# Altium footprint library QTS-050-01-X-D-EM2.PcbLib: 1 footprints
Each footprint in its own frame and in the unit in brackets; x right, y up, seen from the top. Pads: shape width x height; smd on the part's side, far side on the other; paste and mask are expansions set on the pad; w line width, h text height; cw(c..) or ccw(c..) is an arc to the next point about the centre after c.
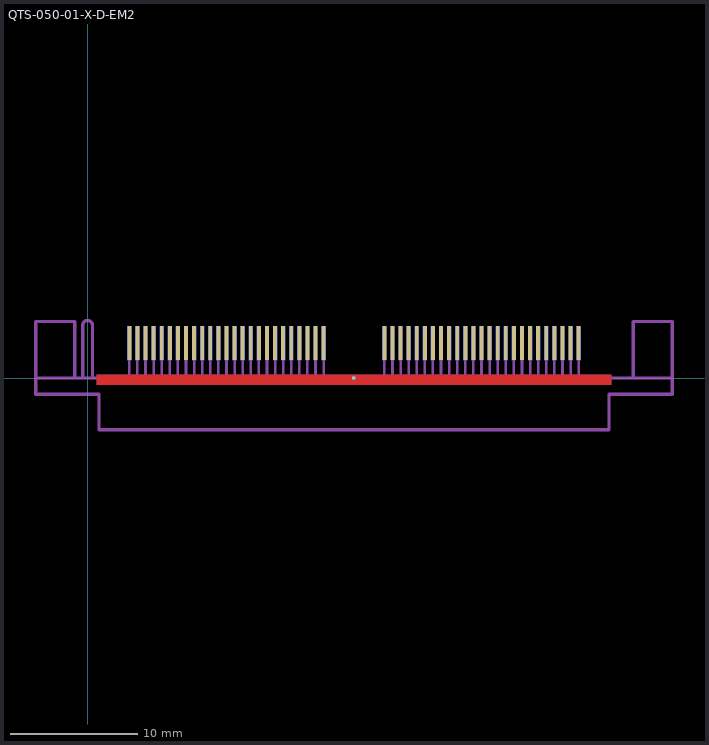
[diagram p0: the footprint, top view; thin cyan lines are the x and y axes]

## QTS-050-01-X-D-EM2 [mil] "0.635mm pitch, 100 pin, high speed terminal; w/edge mounts"
height 117.72
pads (102):
  rect 12x105 smd mask+0: 1(128.8,107.5) 3(153.8,107.5) 5(178.8,107.5) 7(203.8,107.5) 9(228.8,107.5) 11(253.8,107.5) 13(278.8,107.5) 15(303.8,107.5) 17(328.8,107.5) 19(353.8,107.5) 21(378.8,107.5) 23(403.8,107.5) 25(428.8,107.5) 27(453.8,107.5) 29(478.8,107.5) 31(503.8,107.5) 33(528.8,107.5) 35(553.8,107.5) 37(578.8,107.5) 39(603.8,107.5) 41(628.8,107.5) 43(653.8,107.5) 45(678.8,107.5) 47(703.8,107.5) 49(728.8,107.5) 51(916.3,107.5) 53(941.3,107.5) 55(966.3,107.5) 57(991.3,107.5) 59(1016.3,107.5) 61(1041.3,107.5) 63(1066.3,107.5) 65(1091.3,107.5) 67(1116.3,107.5) 69(1141.3,107.5) 71(1166.3,107.5) 73(1191.3,107.5) 75(1216.3,107.5) 77(1241.3,107.5) 79(1266.3,107.5) 81(1291.3,107.5) 83(1316.3,107.5) 85(1341.3,107.5) 87(1366.3,107.5) 89(1391.3,107.5) 91(1416.3,107.5) 93(1441.3,107.5) 95(1466.3,107.5) 97(1491.3,107.5) 99(1516.3,107.5)
  rect 12x105 smd far side mask+0: 2(128.8,107.5) 4(153.8,107.5) 6(178.8,107.5) 8(203.8,107.5) 10(228.8,107.5) 12(253.8,107.5) 14(278.8,107.5) 16(303.8,107.5) 18(328.8,107.5) 20(353.8,107.5) 22(378.8,107.5) 24(403.8,107.5) 26(428.8,107.5) 28(453.8,107.5) 30(478.8,107.5) 32(503.8,107.5) 34(528.8,107.5) 36(553.8,107.5) 38(578.8,107.5) 40(603.8,107.5) 42(628.8,107.5) 44(653.8,107.5) 46(678.8,107.5) 48(703.8,107.5) 50(728.8,107.5) 52(916.3,107.5) 54(941.3,107.5) 56(966.3,107.5) 58(991.3,107.5) 60(1016.3,107.5) 62(1041.3,107.5) 64(1066.3,107.5) 66(1091.3,107.5) 68(1116.3,107.5) 70(1141.3,107.5) 72(1166.3,107.5) 74(1191.3,107.5) 76(1216.3,107.5) 78(1241.3,107.5) 80(1266.3,107.5) 82(1291.3,107.5) 84(1316.3,107.5) 86(1341.3,107.5) 88(1366.3,107.5) 90(1391.3,107.5) 92(1416.3,107.5) 94(1441.3,107.5) 96(1466.3,107.5) 98(1491.3,107.5) 100(1516.3,107.5)
  rect 10x10 smd mask+0: 101(822,0)
  rect 10x10 smd far side mask+0: 102(822,0)
Top Layer:
  region: 28.8,-20 1616.3,-20 1616.3,10 28.8,10
Bottom Layer:
  region: 28.8,-20 1616.3,-20 1616.3,10 28.8,10
Top Solder:
  lines w5: 128.8,114 128.8,160 ; 153.8,114 153.8,160 ; 178.8,114 178.8,160 ; 203.8,114 203.8,160 ; 228.8,114 228.8,160 ; 253.8,114 253.8,160 ; 278.8,114 278.8,160 ; 303.8,114 303.8,160 ; 328.8,114 328.8,160 ; 353.8,114 353.8,160 ; 378.8,114 378.8,160 ; 403.8,114 403.8,160 ; 428.8,114 428.8,160 ; 453.8,114 453.8,160 ; 478.8,114 478.8,160 ; 503.8,114 503.8,160 ; 528.8,114 528.8,160 ; 553.8,114 553.8,160 ; 578.8,114 578.8,160 ; 603.8,114 603.8,160 ; 628.8,114 628.8,160 ; 653.8,114 653.8,160 ; 678.8,114 678.8,160 ; 703.8,114 703.8,160 ; 728.8,114 728.8,160 ; 916.3,114 916.3,160 ; 941.3,114 941.3,160 ; 966.3,114 966.3,160 ; 991.3,114 991.3,160 ; 1016.3,114 1016.3,160 ; 1041.3,114 1041.3,160 ; 1066.3,114 1066.3,160 ; 1091.3,114 1091.3,160 ; 1116.3,114 1116.3,160 ; 1141.3,114 1141.3,160 ; 1166.3,114 1166.3,160 ; 1191.3,114 1191.3,160 ; 1216.3,114 1216.3,160 ; 1241.3,114 1241.3,160 ; 1266.3,114 1266.3,160 ; 1291.3,114 1291.3,160 ; 1316.3,114 1316.3,160 ; 1341.3,114 1341.3,160 ; 1366.3,114 1366.3,160 ; 1391.3,114 1391.3,160 ; 1416.3,114 1416.3,160 ; 1441.3,114 1441.3,160 ; 1466.3,114 1466.3,160 ; 1491.3,114 1491.3,160 ; 1516.3,114 1516.3,160
Bottom Solder:
  lines w5: 128.8,114 128.8,160 ; 153.8,114 153.8,160 ; 178.8,114 178.8,160 ; 203.8,114 203.8,160 ; 228.8,114 228.8,160 ; 253.8,114 253.8,160 ; 278.8,114 278.8,160 ; 303.8,114 303.8,160 ; 328.8,114 328.8,160 ; 353.8,114 353.8,160 ; 378.8,114 378.8,160 ; 403.8,114 403.8,160 ; 428.8,114 428.8,160 ; 453.8,114 453.8,160 ; 478.8,114 478.8,160 ; 503.8,114 503.8,160 ; 528.8,114 528.8,160 ; 553.8,114 553.8,160 ; 578.8,114 578.8,160 ; 603.8,114 603.8,160 ; 628.8,114 628.8,160 ; 653.8,114 653.8,160 ; 678.8,114 678.8,160 ; 703.8,114 703.8,160 ; 728.8,114 728.8,160 ; 916.3,114 916.3,160 ; 941.3,114 941.3,160 ; 966.3,114 966.3,160 ; 991.3,114 991.3,160 ; 1016.3,114 1016.3,160 ; 1041.3,114 1041.3,160 ; 1066.3,114 1066.3,160 ; 1091.3,114 1091.3,160 ; 1116.3,114 1116.3,160 ; 1141.3,114 1141.3,160 ; 1166.3,114 1166.3,160 ; 1191.3,114 1191.3,160 ; 1216.3,114 1216.3,160 ; 1241.3,114 1241.3,160 ; 1266.3,114 1266.3,160 ; 1291.3,114 1291.3,160 ; 1316.3,114 1316.3,160 ; 1341.3,114 1341.3,160 ; 1366.3,114 1366.3,160 ; 1391.3,114 1391.3,160 ; 1416.3,114 1416.3,160 ; 1441.3,114 1441.3,160 ; 1466.3,114 1466.3,160 ; 1491.3,114 1491.3,160 ; 1516.3,114 1516.3,160
Mechanical 13:
  lines w3.94: -39.95,0 -39.95,175 -159.95,175 -159.95,0 ; -15,0 -15,163 cw(c0,163) 15,163 15,0 ; 1685.05,0 1685.05,175 1805.05,175 1805.05,0 ; -159.95,0 1805.05,0 ; -159.95,0 -159.95,-50 35.05,-50 35.05,-160 1610.05,-160 1610.05,-50 1805.05,-50 1805.05,0
  lines w8: 128.8,0 128.8,118 ; 153.8,0 153.8,118 ; 178.8,0 178.8,118 ; 203.8,0 203.8,118 ; 228.8,0 228.8,118 ; 253.8,0 253.8,118 ; 278.8,0 278.8,118 ; 303.8,0 303.8,118 ; 328.8,0 328.8,118 ; 353.8,0 353.8,118 ; 378.8,0 378.8,118 ; 403.8,0 403.8,118 ; 428.8,0 428.8,118 ; 453.8,0 453.8,118 ; 478.8,0 478.8,118 ; 503.8,0 503.8,118 ; 528.8,0 528.8,118 ; 553.8,0 553.8,118 ; 578.8,0 578.8,118 ; 603.8,0 603.8,118 ; 628.8,0 628.8,118 ; 653.8,0 653.8,118 ; 678.8,0 678.8,118 ; 703.8,0 703.8,118 ; 728.8,0 728.8,118 ; 916.3,0 916.3,118 ; 941.3,0 941.3,118 ; 966.3,0 966.3,118 ; 991.3,0 991.3,118 ; 1016.3,0 1016.3,118 ; 1041.3,0 1041.3,118 ; 1066.3,0 1066.3,118 ; 1091.3,0 1091.3,118 ; 1116.3,0 1116.3,118 ; 1141.3,0 1141.3,118 ; 1166.3,0 1166.3,118 ; 1191.3,0 1191.3,118 ; 1216.3,0 1216.3,118 ; 1241.3,0 1241.3,118 ; 1266.3,0 1266.3,118 ; 1291.3,0 1291.3,118 ; 1316.3,0 1316.3,118 ; 1341.3,0 1341.3,118 ; 1366.3,0 1366.3,118 ; 1391.3,0 1391.3,118 ; 1416.3,0 1416.3,118 ; 1441.3,0 1441.3,118 ; 1466.3,0 1466.3,118 ; 1491.3,0 1491.3,118 ; 1516.3,0 1516.3,118
  text ".Designator" at 0,0 h60
Mechanical 14:
  lines w8: 128.8,0 128.8,118 ; 153.8,0 153.8,118 ; 178.8,0 178.8,118 ; 203.8,0 203.8,118 ; 228.8,0 228.8,118 ; 253.8,0 253.8,118 ; 278.8,0 278.8,118 ; 303.8,0 303.8,118 ; 328.8,0 328.8,118 ; 353.8,0 353.8,118 ; 378.8,0 378.8,118 ; 403.8,0 403.8,118 ; 428.8,0 428.8,118 ; 453.8,0 453.8,118 ; 478.8,0 478.8,118 ; 503.8,0 503.8,118 ; 528.8,0 528.8,118 ; 553.8,0 553.8,118 ; 578.8,0 578.8,118 ; 603.8,0 603.8,118 ; 628.8,0 628.8,118 ; 653.8,0 653.8,118 ; 678.8,0 678.8,118 ; 703.8,0 703.8,118 ; 728.8,0 728.8,118 ; 916.3,0 916.3,118 ; 941.3,0 941.3,118 ; 966.3,0 966.3,118 ; 991.3,0 991.3,118 ; 1016.3,0 1016.3,118 ; 1041.3,0 1041.3,118 ; 1066.3,0 1066.3,118 ; 1091.3,0 1091.3,118 ; 1116.3,0 1116.3,118 ; 1141.3,0 1141.3,118 ; 1166.3,0 1166.3,118 ; 1191.3,0 1191.3,118 ; 1216.3,0 1216.3,118 ; 1241.3,0 1241.3,118 ; 1266.3,0 1266.3,118 ; 1291.3,0 1291.3,118 ; 1316.3,0 1316.3,118 ; 1341.3,0 1341.3,118 ; 1366.3,0 1366.3,118 ; 1391.3,0 1391.3,118 ; 1416.3,0 1416.3,118 ; 1441.3,0 1441.3,118 ; 1466.3,0 1466.3,118 ; 1491.3,0 1491.3,118 ; 1516.3,0 1516.3,118
  lines w10: -39.95,0 -39.95,175 -159.95,175 -159.95,0 ; -15,0 -15,163 cw(c0,162.99) 15,162.99 15,0 ; 1685.05,0 1685.05,175 1805.05,175 1805.05,0 ; -159.95,0 -159.95,-50 35.05,-50 35.05,-160 1610.05,-160 1610.05,-50 1805.05,-50 1805.05,0 ; -159.95,0 1805.05,0
Drill Drawing:
  lines w0.39: -125,0 -21.5,0 -21.5,163.5 cw(c0,163.5) 21.5,163.5 21.5,0 1775,0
